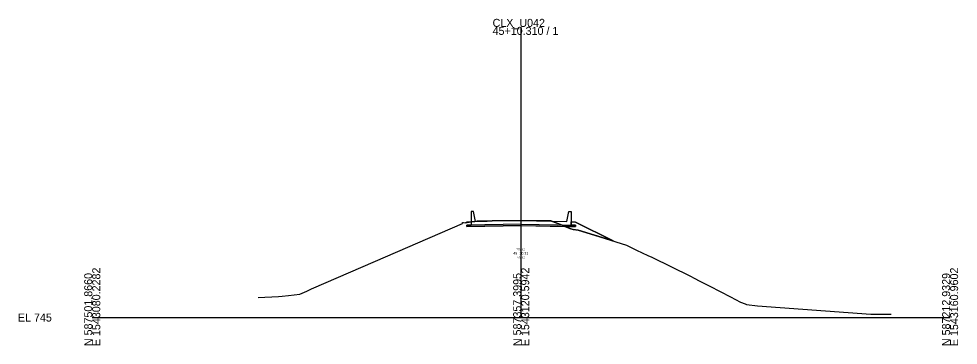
# Model space of a CAD drawing. Extents: x -26 to 1603, y -10 to 5557.
# Drawn here: x -25.7 to 302.8, y 2490.3 to 2604.6 of the extents above; entities that cross this region are included whole.
import ezdxf

# ---------------------------------------------------------------- set-up
doc = ezdxf.new("R2010")
doc.units = 0
for name, color, linetype in [('BR_P_Gen_Approach_Slab', 7, 'Continuous'), ('GK_Cells', 7, 'Continuous'), ('XS_P_Annotation', 7, 'Continuous'), ('XS_P_Earthwork_Shapes', 7, 'Continuous'), ('XS_P_Finished_Grade', 7, 'Continuous'), ('XS_P_Pavt_Layers', 7, 'Continuous'), ('XS_P_Pavt_Surface', 7, 'Continuous'), ('XS_P_Subgrade', 7, 'Continuous'), ('XS_X_Ground_Line', 7, 'Continuous')]:
    doc.layers.add(name, color=color, linetype=linetype)

msp = doc.modelspace()

# ---------------------------------------------------------------- linework, layer by layer
at = {"layer": 'BR_P_Gen_Approach_Slab'}
for p, q in [((132.56, 2537.16), (132.5, 2537.1)), ((132.5, 2537.1), (132.5, 2532.39)), ((133.27, 2537.16), (132.56, 2537.16)), ((133.34, 2537.1), (133.27, 2537.16)), ((134, 2533.66), (133.34, 2537.1)), ((166, 2533.66), (166.66, 2537.1)), ((166.66, 2537.1), (166.73, 2537.16)), ((166.73, 2537.16), (167.44, 2537.16)), ((167.44, 2537.16), (167.5, 2537.1)), ((167.5, 2537.1), (167.5, 2532.39))]:
    msp.add_line(p, q, dxfattribs=at)
at = {"layer": 'GK_Cells'}
for p, q in [((150, 2500), (150, 2601.77)), ((0, 2500), (150, 2500)), ((150, 2500), (300, 2500))]:
    msp.add_line(p, q, dxfattribs=at)
at = {"layer": 'XS_P_Earthwork_Shapes'}
for points in [[(131, 2533.41), (130.58, 2533.2), (132.39, 2533.47), (132.5, 2533.48), (132.5, 2533.54)], [(130.58, 2533.2), (132.39, 2533.47), (132.5, 2533.48), (132.5, 2533.54), (131, 2533.41)], [(130.58, 2533.2), (132.39, 2533.47), (132.5, 2533.48), (132.5, 2533.54), (131, 2533.41)], [(132.5, 2532.39), (131, 2532.37), (131, 2531.87), (150, 2532.17), (165.22, 2531.93), (164.32, 2532.29), (160.32, 2533.82), (149.74, 2533.92), (139.86, 2533.81), (138.11, 2533.79), (136.06, 2533.78), (134.57, 2533.78), (133.85, 2533.6), (132.5, 2533.48)], [(131, 2532.37), (131, 2531.87), (150, 2532.17), (165.22, 2531.93), (164.32, 2532.29), (160.32, 2533.82), (149.74, 2533.92), (139.86, 2533.81), (138.11, 2533.79), (136.06, 2533.78), (134.57, 2533.78), (133.85, 2533.6), (132.5, 2533.48), (132.5, 2532.39)], [(131, 2532.37), (131, 2531.87), (150, 2532.17), (165.22, 2531.93), (164.32, 2532.29), (160.32, 2533.82), (149.74, 2533.92), (139.86, 2533.81), (138.11, 2533.79), (136.06, 2533.78), (134.57, 2533.78), (133.85, 2533.6), (132.5, 2533.48), (132.5, 2532.39)], [(169, 2533.41), (182.12, 2526.85), (175.65, 2528.9), (169.95, 2530.54), (168.2, 2530.78), (167.32, 2531.07), (165.22, 2531.93), (169, 2531.87), (169, 2532.37), (167.5, 2532.39), (167.5, 2533.54)], [(175.65, 2528.9), (182.12, 2526.85), (169, 2533.41), (167.5, 2533.54), (167.5, 2532.39), (169, 2532.37), (169, 2531.87), (165.22, 2531.93), (167.32, 2531.07), (168.2, 2530.78), (169.95, 2530.54)], [(169, 2531.87), (169, 2532.37), (167.5, 2532.39), (167.5, 2533.54), (169, 2533.41), (182.12, 2526.85), (175.65, 2528.9), (169.95, 2530.54), (168.2, 2530.78), (167.32, 2531.07), (165.22, 2531.93)]]:
    msp.add_lwpolyline(points, close=True, dxfattribs=at)
at = {"layer": 'XS_P_Finished_Grade'}
for p, q in [((131, 2533.41), (130.58, 2533.2)), ((132.5, 2533.54), (131, 2533.41)), ((167.5, 2533.54), (169, 2533.41)), ((169, 2533.41), (182.12, 2526.85))]:
    msp.add_line(p, q, dxfattribs=at)
at = {"layer": 'XS_P_Pavt_Layers'}
for p, q in [((150.02, 2532.67), (131, 2532.37)), ((131, 2531.87), (131, 2532.37)), ((150.03, 2532.17), (131, 2531.87)), ((149.97, 2532.17), (169, 2531.87)), ((149.98, 2532.67), (169, 2532.37)), ((169, 2531.87), (169, 2532.37))]:
    msp.add_line(p, q, dxfattribs=at)
at = {"layer": 'XS_P_Pavt_Surface'}
for q in [(134, 2533.66), (166, 2533.66)]:
    msp.add_line((150, 2533.92), q, dxfattribs=at)
at = {"layer": 'XS_P_Subgrade'}
msp.add_lwpolyline([(132.5, 2533.54), (132.5, 2532.39), (131, 2532.37), (131, 2531.87), (150, 2532.17), (169, 2531.87), (169, 2532.37), (167.5, 2532.39), (167.5, 2533.54)], dxfattribs=at)
at = {"layer": 'XS_X_Ground_Line'}
msp.add_lwpolyline([(58.05, 2506.98), (65.18, 2507.41), (66.43, 2507.54), (68.62, 2507.77), (72.56, 2508.19), (75.07, 2509.28), (76.72, 2510), (94.7, 2517.86), (129.43, 2532.98), (129.53, 2533.28), (129.84, 2533.31), (130.52, 2533.19), (132.39, 2533.47), (133.85, 2533.6), (134.57, 2533.78), (136.06, 2533.78), (138.11, 2533.79), (139.86, 2533.81), (149.74, 2533.92), (160.32, 2533.82), (164.32, 2532.29), (167.32, 2531.07), (168.2, 2530.78), (169.95, 2530.54), (175.65, 2528.9), (186.81, 2525.37), (190.31, 2523.55), (194.29, 2521.72), (195.64, 2521.1), (209.22, 2514.48), (210.52, 2513.81), (212.5, 2512.79), (215.92, 2511.02), (223.24, 2507.24), (226.67, 2505.42), (228.28, 2504.75), (228.76, 2504.59), (232.65, 2504.08), (272.26, 2501.22), (275.59, 2501.14), (279.41, 2501.15)], dxfattribs=at)

# ---------------------------------------------------------------- texts
at = {"layer": 'GK_Cells'}
for s, p in [('CLX_U042', (140, 2601.77)), ('45+10.310 / 1', (140, 2598.97)), ('EL 745', (-26, 2498.6))]:
    msp.add_text(s, height=2.8, dxfattribs=at).set_placement(p)
for s, p in [('E 1543080.2282', (2.8, 2490)), ('E 1543120.5942', (152.8, 2490)), ('E 1543160.9602', (302.8, 2490)), ('N 587501.8660', (0, 2490)), ('N 587357.3995', (150, 2490)), ('N 587212.9329', (300, 2490))]:
    msp.add_text(s, height=2.8, rotation=90, dxfattribs=at).set_placement(p)
at = {"layer": 'XS_P_Annotation'}
for s, height, p in [('778.92', 0.7, (148.31, 2523.55)), ('45+10.31', 0.9, (147.27, 2522.05)), ('778.92', 0.7, (148.31, 2520.75))]:
    msp.add_text(s, height=height, dxfattribs=at).set_placement(p)

doc.saveas('drawing.dxf')
